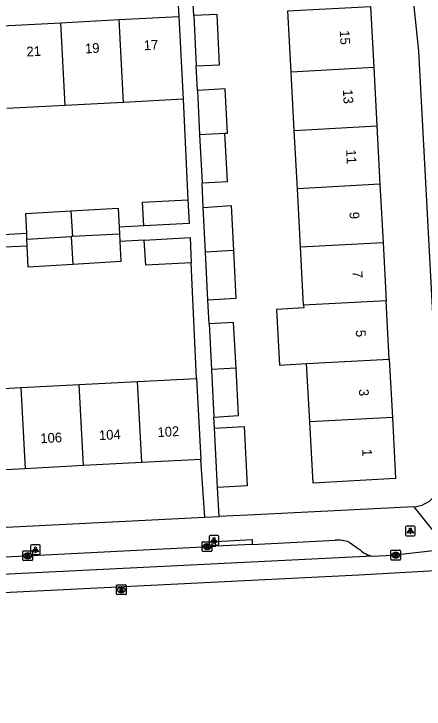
# Model space of a CAD drawing. Extents: x 160557 to 161245, y 385330 to 386505.
# Drawn here: x 161106.4 to 161148.6, y 385334.4 to 385405.9 of the extents above; entities that cross this region are included whole.
import ezdxf

# ---------------------------------------------------------------- set-up
doc = ezdxf.new("R2010")
doc.units = 0
for name, color, linetype in [('IMGEO_Fietspad_gesloten', 7, 'Continuous'), ('IMGEO_Kolk', 7, 'Continuous'), ('IMGEO_Lichtpunt', 7, 'Continuous'), ('IMGEO_Pand', 7, 'Continuous'), ('IMGEO_Pand_nummerreeks', 7, 'Continuous'), ('IMGEO_Rijbaan_lokaal_gesloten', 7, 'Continuous'), ('IMGEO_Rioolput', 7, 'Continuous'), ('IMGEO_Voetpad_open', 7, 'Continuous')]:
    doc.layers.add(name, color=color, linetype=linetype)

msp = doc.modelspace()

# ---------------------------------------------------------------- linework, layer by layer
at = {"layer": 'IMGEO_Fietspad_gesloten'}
for points in [[(161143.272, 385350.151), (161145.316, 385350.247), (161150.976, 385350.908)], [(161143.272, 385350.151), (161085.829, 385347.319)]]:
    msp.add_lwpolyline(points, dxfattribs=at)
at = {"layer": 'IMGEO_Kolk'}
for p, q in [((161125.78, 385350.701), (161125.78, 385351.553)), ((161125.855, 385351.627), (161126.707, 385351.627)), ((161126.268, 385351.407), (161126.293, 385351.407)), ((161126.781, 385351.553), (161126.781, 385350.701)), ((161107.351, 385349.763), (161107.351, 385350.615)), ((161107.426, 385350.689), (161108.278, 385350.689)), ((161107.839, 385350.469), (161107.864, 385350.469)), ((161108.352, 385350.615), (161108.352, 385349.763)), ((161126.707, 385350.627), (161125.855, 385350.627)), ((161126.291, 385350.847), (161126.266, 385350.847)), ((161145.158, 385349.828), (161145.158, 385350.68)), ((161145.233, 385350.754), (161146.085, 385350.754)), ((161145.646, 385350.534), (161145.671, 385350.534)), ((161146.159, 385350.68), (161146.159, 385349.828)), ((161108.278, 385349.689), (161107.426, 385349.689)), ((161107.862, 385349.909), (161107.837, 385349.909)), ((161146.085, 385349.754), (161145.233, 385349.754)), ((161145.669, 385349.974), (161145.644, 385349.974))]:
    msp.add_line(p, q, dxfattribs=at)
for points in [[(161125.78, 385350.701), (161125.78, 385351.553)], [(161125.855, 385351.627), (161126.707, 385351.627)], [(161126.101, 385351.327), (161126.224, 385351.327), (161126.224, 385351.176), (161126.354, 385351.327), (161126.518, 385351.327), (161126.372, 385351.176), (161126.525, 385350.927), (161126.373, 385350.927), (161126.288, 385351.091), (161126.224, 385351.024), (161126.224, 385350.927), (161126.101, 385350.927), (161126.101, 385351.327)], [(161126.781, 385351.553), (161126.781, 385350.701)], [(161107.351, 385349.763), (161107.351, 385350.615)], [(161107.426, 385350.689), (161108.278, 385350.689)], [(161107.672, 385350.389), (161107.795, 385350.389), (161107.795, 385350.238), (161107.925, 385350.389), (161108.089, 385350.389), (161107.943, 385350.238), (161108.096, 385349.989), (161107.944, 385349.989), (161107.859, 385350.153), (161107.795, 385350.086), (161107.795, 385349.989), (161107.672, 385349.989), (161107.672, 385350.389)], [(161108.352, 385350.615), (161108.352, 385349.763)], [(161126.707, 385350.627), (161125.855, 385350.627)], [(161145.158, 385349.828), (161145.158, 385350.68)], [(161145.233, 385350.754), (161146.085, 385350.754)], [(161145.479, 385350.454), (161145.602, 385350.454), (161145.602, 385350.303), (161145.732, 385350.454), (161145.896, 385350.454), (161145.75, 385350.303), (161145.903, 385350.054), (161145.751, 385350.054), (161145.666, 385350.218), (161145.602, 385350.151), (161145.602, 385350.054), (161145.479, 385350.054), (161145.479, 385350.454)], [(161146.159, 385350.68), (161146.159, 385349.828)], [(161108.278, 385349.689), (161107.426, 385349.689)], [(161146.085, 385349.754), (161145.233, 385349.754)]]:
    msp.add_lwpolyline(points, dxfattribs=at)
for centre, start, end in [((161125.857, 385351.551), 91.55205, 178.44795), ((161125.857, 385351.551), 91.55205, 178.44795), ((161126.705, 385351.551), 1.55205, 88.44795), ((161126.705, 385351.551), 1.55205, 88.44795), ((161107.428, 385350.613), 91.55205, 178.44795), ((161107.428, 385350.613), 91.55205, 178.44795), ((161108.276, 385350.613), 1.55205, 88.44795), ((161108.276, 385350.613), 1.55205, 88.44795), ((161125.857, 385350.703), 181.55205, 268.44795), ((161125.857, 385350.703), 181.55205, 268.44795), ((161126.705, 385350.703), 271.55205, 358.44795), ((161126.705, 385350.703), 271.55205, 358.44795), ((161145.235, 385350.678), 91.55205, 178.44795), ((161145.235, 385350.678), 91.55205, 178.44795), ((161146.083, 385350.678), 1.55205, 88.44795), ((161146.083, 385350.678), 1.55205, 88.44795), ((161107.428, 385349.765), 181.55205, 268.44795), ((161107.428, 385349.765), 181.55205, 268.44795), ((161108.276, 385349.765), 271.55205, 358.44795), ((161108.276, 385349.765), 271.55205, 358.44795), ((161145.235, 385349.83), 181.55205, 268.44795), ((161145.235, 385349.83), 181.55205, 268.44795), ((161146.083, 385349.83), 271.55205, 358.44795), ((161146.083, 385349.83), 271.55205, 358.44795)]:
    msp.add_arc(centre, 0.0765, start, end, dxfattribs=at)
for centre, major_axis, ratio, start_param, end_param in [((161126.267, 385351.127), (-0.387, 0.002), 0.722429, 4.712389, 7.853982), ((161126.292, 385351.127), (-0.39, 0.002), 0.717154, 1.570796, 4.712389), ((161107.838, 385350.189), (-0.387, 0.002), 0.722429, 4.712389, 7.853982), ((161107.863, 385350.189), (-0.39, 0.002), 0.717154, 1.570796, 4.712389), ((161145.645, 385350.254), (-0.387, 0.002), 0.722429, 4.712389, 7.853982), ((161145.67, 385350.254), (-0.39, 0.002), 0.717154, 1.570796, 4.712389)]:
    msp.add_ellipse(centre, major_axis=major_axis, ratio=ratio, start_param=start_param, end_param=end_param, dxfattribs=at)
at = {"layer": 'IMGEO_Lichtpunt'}
for p, q in [((161146.658, 385353.14), (161146.658, 385352.333)), ((161146.658, 385353.14), (161146.658, 385352.333)), ((161147.56, 385353.235), (161146.752, 385353.235)), ((161147.56, 385353.235), (161146.752, 385353.235)), ((161147.654, 385352.333), (161147.654, 385353.14)), ((161147.654, 385352.333), (161147.654, 385353.14)), ((161126.492, 385352.171), (161126.492, 385351.364)), ((161126.492, 385352.171), (161126.492, 385351.364)), ((161127.394, 385352.266), (161126.586, 385352.266)), ((161127.394, 385352.266), (161126.586, 385352.266)), ((161127.488, 385351.364), (161127.488, 385352.171)), ((161127.488, 385351.364), (161127.488, 385352.171)), ((161146.752, 385352.239), (161147.56, 385352.239)), ((161146.752, 385352.239), (161147.56, 385352.239)), ((161108.153, 385351.212), (161108.153, 385350.405)), ((161108.153, 385351.212), (161108.153, 385350.405)), ((161109.055, 385351.307), (161108.247, 385351.307)), ((161109.055, 385351.307), (161108.247, 385351.307)), ((161109.149, 385350.405), (161109.149, 385351.212)), ((161109.149, 385350.405), (161109.149, 385351.212)), ((161126.586, 385351.27), (161127.394, 385351.27)), ((161126.586, 385351.27), (161127.394, 385351.27)), ((161108.247, 385350.311), (161109.055, 385350.311)), ((161108.247, 385350.311), (161109.055, 385350.311))]:
    msp.add_line(p, q, dxfattribs=at)
for points in [[(161147.032, 385352.804), (161147.071, 385352.776), (161146.883, 385352.514), (161146.845, 385352.541), (161147.032, 385352.804)], [(161147.134, 385352.756), (161147.181, 385352.756), (161147.181, 385352.434), (161147.134, 385352.434), (161147.134, 385352.756)], [(161147.244, 385352.776), (161147.282, 385352.803), (161147.469, 385352.541), (161147.43, 385352.513), (161147.244, 385352.776)], [(161126.866, 385351.835), (161126.905, 385351.807), (161126.717, 385351.545), (161126.679, 385351.572), (161126.866, 385351.835)], [(161126.968, 385351.787), (161127.015, 385351.787), (161127.015, 385351.465), (161126.968, 385351.465), (161126.968, 385351.787)], [(161127.078, 385351.807), (161127.116, 385351.834), (161127.303, 385351.572), (161127.264, 385351.544), (161127.078, 385351.807)], [(161108.527, 385350.876), (161108.566, 385350.848), (161108.378, 385350.586), (161108.34, 385350.613), (161108.527, 385350.876)], [(161108.629, 385350.828), (161108.676, 385350.828), (161108.676, 385350.506), (161108.629, 385350.506), (161108.629, 385350.828)], [(161108.739, 385350.848), (161108.777, 385350.875), (161108.964, 385350.613), (161108.925, 385350.585), (161108.739, 385350.848)]]:
    msp.add_lwpolyline(points, dxfattribs=at)
for centre in [(161147.157, 385352.938), (161126.991, 385351.969), (161108.652, 385351.01)]:
    msp.add_circle(centre, 0.0994, dxfattribs=at)
for centre, start, end in [((161146.752, 385353.14), 90, 180), ((161146.752, 385353.14), 90, 180), ((161147.56, 385353.14), 0, 90), ((161147.56, 385353.14), 0, 90), ((161126.586, 385352.171), 90, 180), ((161126.586, 385352.171), 90, 180), ((161127.394, 385352.171), 0, 90), ((161127.394, 385352.171), 0, 90), ((161146.752, 385352.333), 180, 270), ((161146.752, 385352.333), 180, 270), ((161147.56, 385352.333), 270, 0), ((161147.56, 385352.333), 270, 360), ((161108.247, 385351.212), 90, 180), ((161108.247, 385351.212), 90, 180), ((161109.055, 385351.212), 0, 90), ((161109.055, 385351.212), 0, 90), ((161126.586, 385351.364), 180, 270), ((161126.586, 385351.364), 180, 270), ((161127.394, 385351.364), 270, 0), ((161127.394, 385351.364), 270, 360), ((161108.247, 385350.405), 180, 270), ((161108.247, 385350.405), 180, 270), ((161109.055, 385350.405), 270, 0), ((161109.055, 385350.405), 270, 360)]:
    msp.add_arc(centre, 0.0946, start, end, dxfattribs=at)
at = {"layer": 'IMGEO_Pand'}
for points in [[(161134.914, 385399.885), (161134.579, 385406.164), (161143.059, 385406.615), (161143.394, 385400.336)], [(161111.269, 385404.948), (161117.261, 385405.267)], [(161117.261, 385405.267), (161123.382, 385405.592)], [(161117.711, 385396.769), (161117.261, 385405.267)], [(161123.382, 385405.592), (161123.834, 385397.095)], [(161125.158, 385400.516), (161127.559, 385400.624), (161127.326, 385405.8), (161124.925, 385405.692)], [(161124.925, 385405.692), (161125.158, 385400.516)], [(161105.278, 385404.629), (161111.269, 385404.948)], [(161111.719, 385396.451), (161111.269, 385404.948)], [(161143.394, 385400.336), (161134.914, 385399.885)], [(161143.394, 385400.336), (161143.713, 385394.345)], [(161135.233, 385393.894), (161134.914, 385399.885)], [(161128.118, 385393.598), (161128.382, 385393.612), (161128.134, 385398.146), (161125.28, 385397.986)], [(161125.28, 385397.986), (161125.509, 385393.459)], [(161117.711, 385396.769), (161111.719, 385396.451)], [(161123.834, 385397.095), (161117.711, 385396.769)], [(161111.719, 385396.451), (161105.728, 385396.132)], [(161135.233, 385393.894), (161143.713, 385394.345)], [(161135.552, 385387.902), (161135.233, 385393.894)], [(161143.713, 385394.345), (161144.032, 385388.353)], [(161125.509, 385393.459), (161128.118, 385393.598)], [(161125.509, 385393.459), (161125.759, 385388.494)], [(161125.759, 385388.494), (161128.361, 385388.652), (161128.118, 385393.598)], [(161144.032, 385388.353), (161135.552, 385387.902)], [(161144.032, 385388.353), (161144.351, 385382.362)], [(161135.871, 385381.911), (161135.552, 385387.902)], [(161119.794, 385384.082), (161119.657, 385386.508), (161124.318, 385386.77)], [(161124.318, 385386.77), (161124.455, 385384.332), (161119.794, 385384.082)], [(161125.887, 385385.972), (161128.77, 385386.158), (161128.993, 385381.545)], [(161126.118, 385381.391), (161125.887, 385385.972)], [(161107.754, 385383.341), (161107.665, 385385.366), (161112.301, 385385.622)], [(161112.301, 385385.622), (161117.139, 385385.889), (161117.239, 385383.942)], [(161112.301, 385385.622), (161112.442, 385382.977)], [(161117.239, 385383.942), (161117.276, 385383.234)], [(161107.781, 385382.729), (161107.754, 385383.341)], [(161117.276, 385383.234), (161112.442, 385382.977)], [(161117.276, 385383.234), (161117.315, 385382.486)], [(161107.781, 385382.729), (161112.334, 385382.971)], [(161107.814, 385382), (161107.781, 385382.729)], [(161112.442, 385382.977), (161112.334, 385382.971)], [(161112.334, 385382.971), (161112.484, 385380.112)], [(161117.315, 385382.486), (161117.422, 385380.403), (161112.484, 385380.112)], [(161119.823, 385382.622), (161124.535, 385382.871), (161124.658, 385380.293)], [(161124.658, 385380.293), (161119.997, 385380.044), (161119.823, 385382.622)], [(161112.484, 385380.112), (161107.909, 385379.842), (161107.814, 385382)], [(161135.871, 385381.911), (161144.351, 385382.362)], [(161136.19, 385375.919), (161135.871, 385381.911)], [(161144.351, 385382.362), (161144.67, 385376.37)], [(161128.993, 385381.545), (161126.118, 385381.391)], [(161126.368, 385376.433), (161126.118, 385381.391)], [(161128.993, 385381.545), (161129.231, 385376.608), (161126.368, 385376.433)], [(161144.67, 385376.37), (161136.19, 385375.919)], [(161144.989, 385370.378), (161144.67, 385376.37)], [(161136.19, 385375.919), (161136.205, 385375.644), (161133.401, 385375.495), (161133.705, 385369.778), (161136.509, 385369.927)], [(161129.258, 385369.458), (161129.005, 385374.17), (161126.49, 385374.008)], [(161126.49, 385374.008), (161126.726, 385369.323)], [(161136.509, 385369.927), (161144.989, 385370.378)], [(161144.989, 385370.378), (161145.309, 385364.387)], [(161136.829, 385363.936), (161136.509, 385369.927)], [(161129.258, 385369.458), (161126.726, 385369.323)], [(161126.726, 385369.323), (161126.973, 385364.435)], [(161126.973, 385364.435), (161129.518, 385364.596), (161129.258, 385369.458)], [(161119.134, 385368.095), (161125.21, 385368.414)], [(161125.21, 385368.414), (161125.647, 385360.086)], [(161101.159, 385367.15), (161107.151, 385367.465)], [(161107.151, 385367.465), (161113.142, 385367.78)], [(161107.151, 385367.465), (161107.588, 385359.137)], [(161113.142, 385367.78), (161119.134, 385368.095)], [(161113.579, 385359.452), (161113.142, 385367.78)], [(161119.571, 385359.767), (161119.134, 385368.095)], [(161145.309, 385364.387), (161145.643, 385358.111), (161137.163, 385357.66), (161136.829, 385363.936)], [(161145.309, 385364.387), (161136.829, 385363.936)], [(161127.03, 385363.314), (161130.103, 385363.471), (161130.414, 385357.358), (161127.341, 385357.202)], [(161127.341, 385357.202), (161127.03, 385363.314)], [(161119.571, 385359.767), (161113.579, 385359.452)], [(161125.647, 385360.086), (161119.571, 385359.767)], [(161107.588, 385359.137), (161101.596, 385358.822)], [(161113.579, 385359.452), (161107.588, 385359.137)]]:
    msp.add_lwpolyline(points, dxfattribs=at)
at = {"layer": 'IMGEO_Rijbaan_lokaal_gesloten'}
msp.add_lwpolyline([(161179.212, 385352.808), (161177.568, 385352.385), (161171.027, 385350.994), (161157.592, 385349.093), (161141.871, 385348.183), (161034.402, 385342.87), (160939.068, 385337.926), (160868.279, 385334.438)], dxfattribs=at)
at = {"layer": 'IMGEO_Rioolput'}
for p, q in [((161116.979, 385346.276), (161116.979, 385347.128)), ((161117.054, 385347.202), (161117.906, 385347.202)), ((161117.467, 385346.982), (161117.492, 385346.982)), ((161117.98, 385347.128), (161117.98, 385346.276)), ((161117.906, 385346.202), (161117.054, 385346.202)), ((161117.49, 385346.422), (161117.465, 385346.422))]:
    msp.add_line(p, q, dxfattribs=at)
for points in [[(161116.979, 385346.276), (161116.979, 385347.128)], [(161117.054, 385347.202), (161117.906, 385347.202)], [(161117.568, 385346.9), (161117.316, 385346.902), (161117.316, 385346.502)], [(161117.494, 385346.821), (161117.44, 385346.821), (161117.44, 385346.74)], [(161117.44, 385346.74), (161117.492, 385346.74)], [(161117.98, 385347.128), (161117.98, 385346.276)], [(161117.906, 385346.202), (161117.054, 385346.202)], [(161117.316, 385346.502), (161117.44, 385346.502), (161117.44, 385346.664), (161117.451, 385346.664)], [(161117.498, 385346.635), (161117.569, 385346.502), (161117.709, 385346.502), (161117.644, 385346.628)]]:
    msp.add_lwpolyline(points, dxfattribs=at)
for centre, radius, start, end in [((161117.056, 385347.126), 0.0765, 91.55205, 178.44795), ((161117.056, 385347.126), 0.0765, 91.55205, 178.44795), ((161117.476, 385346.929), 0.19, 274.7715, 282.96867), ((161117.5, 385346.725), 0.0964, 77.00612, 93.18647), ((161117.514, 385346.782), 0.0378, 276.66336, 79.67722), ((161117.567, 385346.79), 0.109, 350.36119, 89.41601), ((161117.565, 385346.79), 0.112, 277.58423, 350.98172), ((161117.904, 385347.126), 0.0765, 1.55205, 88.44795), ((161117.904, 385347.126), 0.0765, 1.55205, 88.44795), ((161117.056, 385346.278), 0.0765, 181.55205, 268.44795), ((161117.056, 385346.278), 0.0765, 181.55205, 268.44795), ((161117.45, 385346.611), 0.0533, 26.02933, 88.69889), ((161117.549, 385346.575), 0.108, 29.51342, 73.79051), ((161117.904, 385346.278), 0.0765, 271.55205, 358.44795), ((161117.904, 385346.278), 0.0765, 271.55205, 358.44795)]:
    msp.add_arc(centre, radius, start, end, dxfattribs=at)
for centre, major_axis, ratio, start_param, end_param in [((161117.466, 385346.702), (-0.387, 0.002), 0.722429, 4.712389, 7.853982), ((161117.491, 385346.702), (-0.39, 0.002), 0.717154, 1.570796, 4.712389)]:
    msp.add_ellipse(centre, major_axis=major_axis, ratio=ratio, start_param=start_param, end_param=end_param, dxfattribs=at)
at = {"layer": 'IMGEO_Voetpad_open'}
for points in [[(161123.04, 385411.174), (161123.382, 385405.592)], [(161124.925, 385405.692), (161124.564, 385411.253)], [(161147.18, 385409.927), (161147.997, 385402.036), (161150.308, 385358.346)], [(161125.28, 385397.986), (161125.158, 385400.516)], [(161123.834, 385397.095), (161124.318, 385386.77)], [(161125.887, 385385.972), (161125.759, 385388.494)], [(161119.794, 385384.082), (161117.239, 385383.942)], [(161105.302, 385383.21), (161107.754, 385383.341)], [(161119.823, 385382.622), (161117.315, 385382.486)], [(161107.814, 385382), (161105.396, 385381.876)], [(161125.21, 385368.414), (161124.658, 385380.293)], [(161126.49, 385374.008), (161126.368, 385376.433)], [(161127.03, 385363.314), (161126.973, 385364.435)], [(161126.04, 385354.145), (161125.647, 385360.086)], [(161127.536, 385354.22), (161127.341, 385357.202)], [(161147.502, 385355.224), (161131.882, 385354.439), (161127.536, 385354.22)], [(161147.502, 385355.224), (161150.976, 385350.908)], [(161088.643, 385352.265), (161126.04, 385354.145)], [(161126.04, 385354.145), (161127.536, 385354.22)], [(161127.164, 385351.171), (161127.143, 385351.67), (161130.901, 385351.861), (161130.922, 385351.362)], [(161130.922, 385351.362), (161139.434, 385351.795)], [(161086.601, 385349.107), (161127.164, 385351.171)], [(161130.922, 385351.362), (161127.164, 385351.171)], [(161140.869, 385351.587), (161142.003, 385350.792)]]:
    msp.add_lwpolyline(points, dxfattribs=at)
for centre, radius, start, end in [((161147.348, 385358.184), 2.964, 272.97566, 3.12702), ((161139.639, 385348.152), 3.648, 70.2904, 93.21469), ((161143.668, 385352.511), 2.393, 225.92251, 260.47879)]:
    msp.add_arc(centre, radius, start, end, dxfattribs=at)

# ---------------------------------------------------------------- texts
at = {"layer": 'IMGEO_Pand_nummerreeks'}
for s, rotation, p in [('15', 273.04949, (161139.906, 385404.143)), ('17', 3.04327, (161119.805, 385402.117)), ('21', 3.04327, (161107.757, 385401.476)), ('19', 3.04327, (161113.77, 385401.796)), ('13', 273.04949, (161140.229, 385398.08)), ('11', 273.04949, (161140.558, 385391.903)), ('9', 273.04949, (161140.9, 385385.494)), ('7', 273.04949, (161141.223, 385379.431)), ('5', 273.04793, (161141.546, 385373.368)), ('3', 273.04949, (161141.869, 385367.305)), ('104', 3.00829, (161115.2, 385362.061)), ('102', 3.00829, (161121.217, 385362.377)), ('106', 3.00829, (161109.18, 385361.744)), ('1', 273.04949, (161142.198, 385361.129))]:
    msp.add_text(s, height=1, rotation=rotation, dxfattribs=at).set_placement(p)

doc.saveas('drawing.dxf')
